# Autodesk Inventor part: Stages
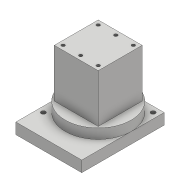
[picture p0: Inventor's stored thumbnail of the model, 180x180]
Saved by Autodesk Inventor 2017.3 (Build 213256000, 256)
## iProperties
Part Number: Stages
Material: 一般
Document SubType Name: Modeling
Designer: kyushu-hep
Density: 1 g/cm^3
Appearance: 既定
Author: kyushu-hep
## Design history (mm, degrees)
sketch "スケッチ1"
  geometry: L1 (30, -37.5)-(-30, -37.5); L2 (-30, -37.5)-(-30, 37.5); L3 (-30, 37.5)-(30, 37.5); L4 (30, 37.5)-(30, -37.5); L5 (30, -37.5)-(-30, 37.5); L6 (-30, -37.5)-(30, 37.5); 1 further point
  constraints: 12 end point, 2 midpoint, 2 parallel, 1 horizontal, 1 perpendicular
  dimensions: "d0" = 60 distance of L2.end L3.end; "d1" = 75 distance of L3.end L1.start
extrude "押し出し1" new body sketch "スケッチ1" distance "d2" = 10; taper "d3" = 0 deg
sketch "スケッチ2"
  geometry: L1 (-30, 37.5)-(-30, -37.5) reference; L2 (30, 37.5)-(-30, 37.5) reference; C1 r 30 at (0, 7.5); 1 further point
  constraints: 2 tangent, 1 centre point
  dimensions: "d4" = 60 diameter of C1
extrude "押し出し2" join sketch "スケッチ2" distance "d5" = 9; taper "d6" = 0 deg
sketch "スケッチ3"
  geometry: L1 (-30, 7.5)-(-30, -37.5) reference; L2 (-30, 37.5)-(-30, 7.5) reference; L3 (0, 37.5)-(-30, 37.5) reference; L4 (30, 37.5)-(0, 37.5) reference; C1 r 2 at (-25, -17.5); C2 r 2 at (-25, 32.5); C3 r 2 at (25, 32.5); 1 further point
  constraints: 3 centre point
  dimensions: "d7" = 4 diameter of C1; "d8" = 4 diameter of C2; "d9" = 4 diameter of C3; "d10" = 50 distance of C1.centre C2.centre; "d11" = 5 distance from line of L1 C1.centre; "d12" = 5 distance from line of L2 C2.centre; "d13" = 5 distance from line of L3 C2.centre; "d14" = 50 distance of C2.centre C3.centre; "d15" = 5 distance from line of L4 C3.centre
extrude "押し出し3" cut sketch "スケッチ3" distance "d16" = 10; taper "d17" = 0 deg
sketch "スケッチ4"
  geometry: L1 (20, 20)-(-20, 20); L2 (-20, 20)-(-20, -20); L3 (-20, -20)-(20, -20); L4 (20, -20)-(20, 20); L5 (20, 20)-(-20, -20); L6 (-20, 20)-(20, -20); 2 further points
  constraints: 12 end point, 2 midpoint, 2 parallel, 1 horizontal, 1 perpendicular
  dimensions: "d18" = 40 distance of L3.end L2.end; "d19" = 40 distance of L2.end L1.end
extrude "押し出し4" join sketch "スケッチ4" distance "d20" = 44; taper "d21" = 0 deg
sketch "スケッチ5"
  geometry: L1 (20, 20)-(-20, 20) reference; L2 (-20, -20)-(20, -20) reference; L3 (-20, 20)-(20, 20); L4 (20, 20)-(20, -20); L5 (20, -20)-(-20, -20); L6 (-20, -20)-(-20, 20); C1 r 1.5 at (-16, 16); C2 r 1.5 at (0, 16); C3 r 1.5 at (16, 16); C4 r 1.5 at (-16, -16); C5 r 1.5 at (0, -16); C6 r 1.5 at (16, -16); 1 further point
  constraints: 8 end point, 6 centre point, 2 horizontal, 2 parallel, 1 perpendicular, 1 vertical, 10 other
  dimensions: "d22" = 3 diameter of C1; "d23" = 23.5 vertical distance of point (0, -7.5) C1.centre; "d24" = 16 horizontal distance of C1.centre point (0, -7.5); "d27" = 16 distance of C1.centre C2.centre; "d30" = 32 distance of C1.centre C4.centre
extrude "押し出し5" cut sketch "スケッチ5" distance "d33" = 7; taper "d34" = 0 deg
feature "ねじ1" dims "d35" = 10, "d36" = 0
feature "ねじ2" dims "d37" = 10, "d38" = 0
feature "ねじ3" dims "d39" = 10, "d40" = 0
feature "ねじ4" dims "d41" = 10, "d42" = 0
feature "ねじ5" dims "d43" = 10, "d44" = 0
feature "ねじ6" dims "d45" = 10, "d46" = 0
feature "ねじ7" dims "d47" = 10, "d48" = 0
feature "ねじ8" dims "d49" = 10, "d50" = 0
feature "ねじ9" dims "d51" = 10, "d52" = 0
node "ソリッド1"
